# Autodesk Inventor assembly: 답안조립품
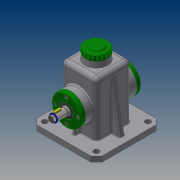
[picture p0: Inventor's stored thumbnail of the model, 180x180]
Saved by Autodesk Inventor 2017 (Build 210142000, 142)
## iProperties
Part Number: 답안조립품
Material: 일반
Document SubType Name: Assembly
Designer: 20
Author: 20
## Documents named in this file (14)
- C:\Users\20\Desktop\470818V1013\답안조립품.iam
- C:\Users\20\Desktop\470818V1013\본체.ipt
- C:\Users\20\Desktop\470818V1013\축.ipt
- C:\Users\20\Desktop\470818V1013\키 5 x 5 x 14.ipt
- C:\Users\20\Desktop\470818V1013\앞커버.ipt
- C:\Users\20\Desktop\470818V1013\오일실 15 25 7.ipt
- C:\Users\20\Desktop\470818V1013\베어링 15 x 35 x 11.ipt
- C:\Users\20\Desktop\470818V1013\멈춤링 15 x 1.ipt
- C:\Users\20\Desktop\470818V1013\뒤커버.ipt
- C:\Users\20\Desktop\470818V1013\상부캡.ipt
- C:\Users\20\Desktop\470818V1013\V-벨트풀리.ipt
- C:\Users\20\Desktop\470818V1013\볼트 M6 x 12.ipt
- C:\Users\20\Desktop\470818V1013\와셔.ipt
- C:\Users\20\Desktop\470818V1013\볼트 M4 x 10.ipt
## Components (1 placed, 1 different names)
1. V-벨트풀리:1
